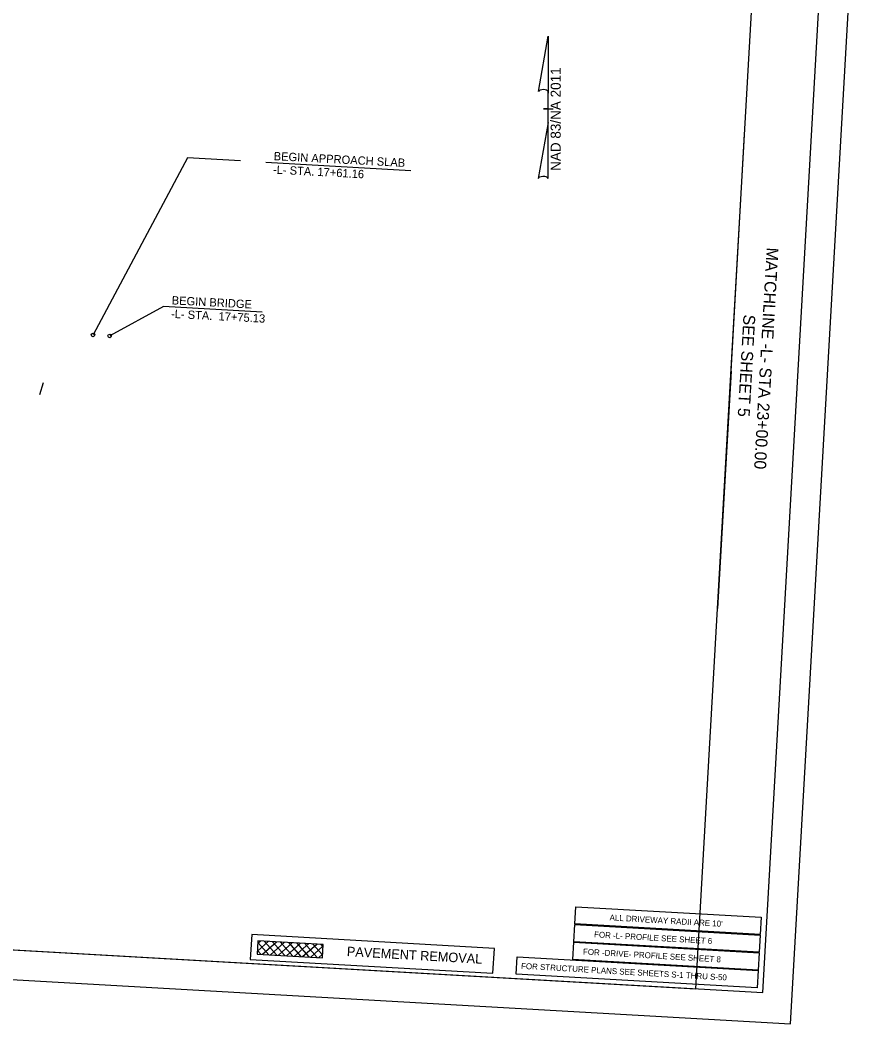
# Model space of a CAD drawing. Extents: x 2602909 to 2604669, y 617940 to 619640.
# Drawn here: x 2603958 to 2604669, y 617940 to 618785 of the extents above; entities that cross this region are included whole.
import ezdxf

# ---------------------------------------------------------------- set-up
doc = ezdxf.new("R2010")
doc.units = 0
for name, color, linetype in [('Prop DSN Text', 7, 'Continuous'), ('Prop Grid Mask', 7, 'Continuous'), ('Prop Horizontal Alignment', 7, 'Continuous'), ('Prop Horizontal Alignment Station Label', 7, 'Continuous'), ('Prop North Arrow NAD83 for Plan Sheets CELL', 7, 'Continuous'), ('Prop Rem of Exist Asph Pvmt', 7, 'Continuous'), ('Scratch_Level_1', 7, 'Continuous'), ('Sheet Plan And Profile CELL', 7, 'Continuous'), ('Stewart Plot Border Xerox6279 and LJ5000', 7, 'Continuous'), ('Typical Terminator CELL', 7, 'Continuous')]:
    doc.layers.add(name, color=color, linetype=linetype)

msp = doc.modelspace()

# ---------------------------------------------------------------- linework, layer by layer
at = {"layer": 'Prop Grid Mask'}
for points in [[(2604151.35, 617994.28), (2604355.65, 617982.64), (2604356.84, 618003.52), (2604152.53, 618015.16)], [(2604212.65, 618006.9), (2604157.84, 618010.02), (2604157.2, 617998.78), (2604212.01, 617995.66)]]:
    msp.add_lwpolyline(points, close=True, dxfattribs=at)
at = {"layer": 'Prop Horizontal Alignment'}
for q in [(2604567.6, 618689.27), (2604544.85, 618289.91)]:
    msp.add_line((2604556.22, 618489.59), q, dxfattribs=at)
at = {"layer": 'Prop Horizontal Alignment Station Label'}
for p, q in [((2604098.6, 618669.24), (2604018.97, 618520.19)), ((2604143.04, 618666.71), (2604098.6, 618669.24)), ((2604286.59, 618658.53), (2604164.45, 618665.49)), ((2604078.21, 618544.02), (2604032.95, 618519.39)), ((2604161.25, 618539.29), (2604078.21, 618544.02))]:
    msp.add_line(p, q, dxfattribs=at)
for points in [[(2604580.69, 618015.19), (2604424.71, 618024.07), (2604425.54, 618038.59), (2604581.52, 618029.71)], [(2604579.84, 618000.24), (2604423.86, 618009.12), (2604424.69, 618023.64), (2604580.67, 618014.76)], [(2604578.99, 617985.29), (2604423.01, 617994.17), (2604423.84, 618008.69), (2604579.82, 617999.81)], [(2604578.14, 617970.34), (2604375.33, 617981.89), (2604376.16, 617996.41), (2604578.96, 617984.86)]]:
    msp.add_lwpolyline(points, close=True, dxfattribs=at)
for centre in [(2604018.97, 618520.19), (2604032.95, 618519.39)]:
    msp.add_circle(centre, 1.5, dxfattribs=at)
at = {"layer": 'Prop North Arrow NAD83 for Plan Sheets CELL'}
for p, q in [((2604393.98, 618725.34), (2604402.21, 618771.69)), ((2604402.26, 618771.69), (2604402.21, 618771.69)), ((2604402.26, 618771.69), (2604402.21, 618771.69)), ((2604402.26, 618771.69), (2604402.23, 618723.89)), ((2604402.22, 618699.09), (2604402.23, 618725.29)), ((2604402.23, 618723.89), (2604402.23, 618725.24)), ((2604398.22, 618710.69), (2604398.17, 618710.69)), ((2604401.77, 618710.69), (2604398.22, 618710.69)), ((2604398.27, 618710.69), (2604406.27, 618710.69)), ((2604402.22, 618699.09), (2604393.84, 618651.84)), ((2604402.24, 618652.04), (2604402.22, 618699.09))]:
    msp.add_line(p, q, dxfattribs=at)
for centre, start_param, end_param in [((2604398.12, 618724.85), 0.216388, 2.908219), ((2604398.07, 618651.68), 0.201328, 3.141593)]:
    msp.add_ellipse(centre, major_axis=(4.23, -0.03), ratio=0.461098, start_param=start_param, end_param=end_param, dxfattribs=at)
at = {"layer": 'Prop Rem of Exist Asph Pvmt'}
for p, q in [((2604157.34, 618001.21), (2604166.65, 618009.52)), ((2604157.72, 618007.99), (2604159.87, 618009.91)), ((2604161.54, 617998.53), (2604173.43, 618009.13)), ((2604163.05, 618009.73), (2604173.66, 617997.84)), ((2604169.83, 618009.34), (2604180.43, 617997.46)), ((2604176.61, 618008.95), (2604187.21, 617997.07)), ((2604157.36, 618001.68), (2604160.1, 617998.61)), ((2604157.75, 618008.46), (2604166.88, 617998.23)), ((2604168.32, 617998.15), (2604180.21, 618008.75)), ((2604175.1, 617997.76), (2604186.98, 618008.36)), ((2604181.88, 617997.37), (2604193.76, 618007.98)), ((2604183.39, 618008.57), (2604193.99, 617996.68)), ((2604188.66, 617996.99), (2604200.54, 618007.59)), ((2604190.16, 618008.18), (2604200.77, 617996.3)), ((2604195.43, 617996.6), (2604207.32, 618007.2)), ((2604196.94, 618007.8), (2604207.55, 617995.91)), ((2604202.21, 617996.22), (2604212.57, 618005.46)), ((2604203.72, 618007.41), (2604212.14, 617997.97)), ((2604210.5, 618007.02), (2604212.53, 618004.75)), ((2604208.99, 617995.83), (2604212.18, 617998.68))]:
    msp.add_line(p, q, dxfattribs=at)
at = {"layer": 'Scratch_Level_1'}
msp.add_lwpolyline([(2604574.88, 618817.07), (2604431.33, 618825.24), (2604442.75, 619025.97), (2603144.9, 619099.88), (2603085.2, 618051.58), (2604526.6, 617969.49)], close=True, dxfattribs=at)
msp.add_lwpolyline([(2604574.88, 618817.07), (2604431.33, 618825.24), (2604442.75, 619025.97), (2603144.9, 619099.88), (2603085.2, 618051.58), (2604526.6, 617969.49)], close=True, dxfattribs=at)
at = {"layer": 'Sheet Plan And Profile CELL'}
msp.add_lwpolyline([(2604642.48, 619014.59), (2603144.9, 619099.88), (2603085.2, 618051.58), (2604582.77, 617966.29)], close=True, dxfattribs=at)
at = {"layer": 'Stewart Plot Border Xerox6279 and LJ5000'}
msp.add_lwpolyline([(2602909.06, 618036.57), (2604606.31, 617939.91), (2604668.86, 619038.13), (2602971.61, 619134.8)], close=True, dxfattribs=at)
at = {"layer": 'Typical Terminator CELL'}
msp.add_line((2603976.98, 618479.87), (2603973.98, 618469.84), dxfattribs=at)

# ---------------------------------------------------------------- texts
at = {"layer": 'Prop DSN Text'}
msp.add_text('PAVEMENT REMOVAL', height=8, rotation=356.74026, dxfattribs=at).set_placement((2604232.48, 617997.07))
at = {"layer": 'Prop Horizontal Alignment'}
for s, p in [('MATCHLINE -L- STA 23+00.00', (2604586.15, 618593.97)), ('SEE SHEET 5', (2604566.67, 618537.56))]:
    msp.add_text(s, height=10, rotation=266.74026, dxfattribs=at).set_placement(p)
at = {"layer": 'Prop Horizontal Alignment Station Label'}
for s, height, rotation, p in [('BEGIN APPROACH SLAB', 7, 357.0037, (2604170.93, 618667.44)), ('-L- STA. 17+61.16', 7, 357.0037, (2604170.34, 618656.08)), ('BEGIN BRIDGE', 7, 357.0037, (2604085.06, 618545.95)), ('-L- STA.  17+75.13', 7, 357.0037, (2604084.46, 618534.59)), ("ALL DRIVEWAY RADII ARE 10'", 5, 356.74026, (2604453.78, 618027.09)), ('FOR -L- PROFILE SEE SHEET 6', 5, 356.74026, (2604440.73, 618012.84)), ('FOR -DRIVE- PROFILE SEE SHEET 8', 5, 356.74026, (2604431.37, 617998.37)), ('FOR STRUCTURE PLANS SEE SHEETS S-1 THRU S-50', 5, 356.74026, (2604379.24, 617986.34))]:
    msp.add_text(s, height=height, rotation=rotation, dxfattribs=at).set_placement(p)
at = {"layer": 'Prop North Arrow NAD83 for Plan Sheets CELL'}
msp.add_text('NAD 83/NA 2011', height=8.5, rotation=89.96355, dxfattribs=at).set_placement((2604412.71, 618658.34))

doc.saveas('drawing.dxf')
